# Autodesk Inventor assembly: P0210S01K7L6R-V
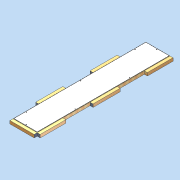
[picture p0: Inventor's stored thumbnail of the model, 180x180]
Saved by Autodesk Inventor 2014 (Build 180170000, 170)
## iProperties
Created: 2011-04
Part Number: P0210S01K7L6R-V
Document SubType Name: Assembly
Designer: david.appleford
Mass: 36000 g
Surface Area: 48094.5 cm^2
Volume: 144709 cm^3
Density: 0.248775 g/cm^3
Description: 0.5w x 2.5w 01 Panel - 7 Locks 6 Lugs RH
Cost Center: £141.00
Justset: False
Author: david.appleford
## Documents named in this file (5)
- C:\Documents and Settings\john.everitt\Local Settings\My Documents\Vault\Production MkII\VIRTUAL ELEMENTS\Virtual Walls\Virtual Timber + MgO\P0210S01K7L6R-V.iam
- C:\Documents and Settings\john.everitt\Local Settings\My Documents\Vault\Production MkII\VIRTUAL ELEMENTS\Virtual Lugs\Superceded Lugs\LA02C3V.ipt
- C:\Documents and Settings\john.everitt\Local Settings\My Documents\Vault\Production MkII\VIRTUAL ELEMENTS\Virtual Lugs\Superceded Lugs\LA02M3V.ipt
- C:\Documents and Settings\john.everitt\Local Settings\My Documents\Vault\Production MkII\VIRTUAL ELEMENTS\Virtual Walls\Virtual Timber + MgO\P0210S01K7-V.ipt
- C:\Documents and Settings\john.everitt\Local Settings\My Documents\Vault\Production MkII\VIRTUAL ELEMENTS\Virtual Lugs\Superceded Lugs\LA02E3V.ipt
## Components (7 placed, 4 different names)
1. P0210S01K7-V:1 — Mate:1, Flush:1, Flush:2, Mate:5, Mate:6, Flush:9, Flush:10, Mate:7, Mate:8, Flush:11, Flush:12, Flush:13, Flush:14, Mate:14
2. LA02C3V:1 — Mate:1, Flush:1, Flush:2, Mate:9, Mate:13
3. LA02M3V:1 — Mate:6, Flush:9, Mate:12
4. LA02M3V:2 — Mate:5, Flush:10, Mate:12, Mate:13
5. LA02C3V:4 — Mate:8, Flush:12, Mate:10
6. LA02M3V:4 — Mate:7, Flush:11, Mate:9, Mate:10
7. LA02E3V:1 — Flush:13, Flush:14, Mate:14
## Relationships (18: Mate 10, Flush 8)
- Mate:1: P0210S01K7-V:1 ↔ LA02C3V:1
- Flush:1: P0210S01K7-V:1 ↔ LA02C3V:1
- Flush:2: P0210S01K7-V:1 ↔ LA02C3V:1
- Mate:5: P0210S01K7-V:1 ↔ LA02M3V:2
- Mate:6: P0210S01K7-V:1 ↔ LA02M3V:1
- Flush:9: P0210S01K7-V:1 ↔ LA02M3V:1
- Flush:10: P0210S01K7-V:1 ↔ LA02M3V:2
- Mate:7: P0210S01K7-V:1 ↔ LA02M3V:4
- Mate:8: P0210S01K7-V:1 ↔ LA02C3V:4
- Flush:11: P0210S01K7-V:1 ↔ LA02M3V:4
- Flush:12: P0210S01K7-V:1 ↔ LA02C3V:4
- Mate:9: LA02C3V:1 ↔ LA02M3V:4
- Mate:10: LA02C3V:4 ↔ LA02M3V:4
- Mate:12: LA02M3V:1 ↔ LA02M3V:2
- Mate:13: LA02C3V:1 ↔ LA02M3V:2
- Flush:13: P0210S01K7-V:1 ↔ LA02E3V:1
- Flush:14: P0210S01K7-V:1 ↔ LA02E3V:1
- Mate:14: P0210S01K7-V:1 ↔ LA02E3V:1
## Named parameters: t = 1 mm, Cl = 2 mm
